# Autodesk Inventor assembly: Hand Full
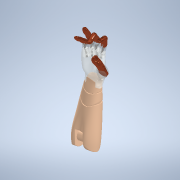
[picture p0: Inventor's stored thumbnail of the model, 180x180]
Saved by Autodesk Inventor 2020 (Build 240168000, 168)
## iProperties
Created: 2019-10
Part Number: Hand Full
Document SubType Name: Assembly
Designer: yello
Author: yello
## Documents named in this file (21)
- D:\1-Cours-2021-22\1STI2D\ETLV\AI\Hand Full.iam
- D:\1-Cours-2021-22\1STI2D\ETLV\AI\Prototype 2 (Realistic Hand)\Palm.ipt
- D:\1-Cours-2021-22\1STI2D\ETLV\AI\Prototype 2 (Realistic Hand)\Wrist Rotation.ipt
- D:\1-Cours-2021-22\1STI2D\ETLV\AI\Prototype 2 (Realistic Hand)\Arm to Wrist Connection.ipt
- D:\1-Cours-2021-22\1STI2D\ETLV\AI\Prototype 2 (Realistic Hand)\Arm.ipt
- D:\1-Cours-2021-22\1STI2D\ETLV\AI\Prototype 2 (Realistic Hand)\Segment Thumb Finger Bottom.ipt
- D:\1-Cours-2021-22\1STI2D\ETLV\AI\Prototype 2 (Realistic Hand)\Segment Thumb Finger Middle.ipt
- D:\1-Cours-2021-22\1STI2D\ETLV\AI\Prototype 2 (Realistic Hand)\Segment Thumb Finger Top.ipt
- D:\1-Cours-2021-22\1STI2D\ETLV\AI\Prototype 2 (Realistic Hand)\Segment Index Finger Middle.ipt
- D:\1-Cours-2021-22\1STI2D\ETLV\AI\Prototype 2 (Realistic Hand)\Segment Index Finger Top.ipt
- D:\1-Cours-2021-22\1STI2D\ETLV\AI\Prototype 2 (Realistic Hand)\Segment Middle Finger Middle.ipt
- D:\1-Cours-2021-22\1STI2D\ETLV\AI\Prototype 2 (Realistic Hand)\Segment Middle Finger Top.ipt
- D:\1-Cours-2021-22\1STI2D\ETLV\AI\Prototype 2 (Realistic Hand)\Segment Ring Finger Middle.ipt
- D:\1-Cours-2021-22\1STI2D\ETLV\AI\Prototype 2 (Realistic Hand)\Segment Ring Finger Top.ipt
- D:\1-Cours-2021-22\1STI2D\ETLV\AI\Prototype 2 (Realistic Hand)\Segment Pinkie Finger Middle.ipt
- D:\1-Cours-2021-22\1STI2D\ETLV\AI\Prototype 2 (Realistic Hand)\Segment Pinkie Finger Top.ipt
- D:\1-Cours-2021-22\1STI2D\ETLV\AI\Prototype 2 (Realistic Hand)\Segment Index Finger Bottom Ball.iam
- D:\1-Cours-2021-22\1STI2D\ETLV\AI\Prototype 2 (Realistic Hand)\Segment Middle Finger Bottom Ball.iam
- D:\1-Cours-2021-22\1STI2D\ETLV\AI\Prototype 2 (Realistic Hand)\Segment Ring Finger Bottom Ball.iam
- D:\1-Cours-2021-22\1STI2D\ETLV\AI\Prototype 2 (Realistic Hand)\Segment Pinkie Finger Bottom Ball.iam
- D:\1-Cours-2021-22\1STI2D\ETLV\AI\Prototype 2 (Realistic Hand)\Bearings.iam
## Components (23 placed, 20 different names)
1. Palm:1 — Rotational:1, Rotational:2, Rotational:17, Rotational:18, Rotational:19, Rotational:20
2. Wrist Rotation:1 — Rotational:1, Mate:1, Mate:2, Mate:4
3. Arm to Wrist Connection:1 — Mate:1, Mate:2, Mate:3
4. Arm:1 — Mate:3, Mate:4
5. Segment Thumb Finger Bottom:1 — Rotational:2, Rotational:3
6. Segment Thumb Finger Middle:1 — Rotational:3, Rotational:4
7. Segment Thumb Finger Top:1 — Rotational:4
8. Segment Index Finger Middle:1 — Rotational:24, Rotational:25, Mate:5, Flush:1
9. Segment Index Finger Top:1 — Rotational:25
10. Segment Middle Finger Middle:1 — Rotational:10, Rotational:23, Mate:6, Flush:2
11. Segment Middle Finger Top:1 — Rotational:10
12. Segment Ring Finger Middle:1 — Rotational:13, Rotational:22, Mate:7, Flush:3
13. Segment Ring Finger Top:1 — Rotational:13
14. Segment Pinkie Finger Middle:1 — Rotational:16, Rotational:21, Mate:8, Flush:4
15. Segment Pinkie Finger Top:1 — Rotational:16
16. Segment Index Finger Bottom Ball:1 [sub-assembly] — Rotational:17, Rotational:24
17. Segment Middle Finger Bottom Ball:1 [sub-assembly] — Rotational:18, Rotational:23
18. Segment Ring Finger Bottom Ball:1 [sub-assembly] — Rotational:19, Rotational:22
19. Segment Pinkie Finger Bottom Ball:1 [sub-assembly] — Rotational:20, Rotational:21
20. Bearings:1 [sub-assembly] — Mate:5, Flush:1
21. Bearings:2 [sub-assembly] — Mate:6, Flush:2
22. Bearings:3 [sub-assembly] — Mate:7, Flush:3
23. Bearings:4 [sub-assembly] — Mate:8, Flush:4
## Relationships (28: RevoluteJoint 16, Mate 8, Flush 4)
- Rotational:1 [RevoluteJoint]: Palm:1 ↔ Wrist Rotation:1
- Mate:1: Wrist Rotation:1 ↔ Arm to Wrist Connection:1
- Mate:2: Wrist Rotation:1 ↔ Arm to Wrist Connection:1
- Mate:3: Arm to Wrist Connection:1 ↔ Arm:1
- Mate:4: Wrist Rotation:1 ↔ Arm:1
- Rotational:2 [RevoluteJoint]: Palm:1 ↔ Segment Thumb Finger Bottom:1
- Rotational:3 [RevoluteJoint]: Segment Thumb Finger Bottom:1 ↔ Segment Thumb Finger Middle:1
- Rotational:4 [RevoluteJoint]: Segment Thumb Finger Middle:1 ↔ Segment Thumb Finger Top:1
- Rotational:10 [RevoluteJoint]: Segment Middle Finger Middle:1 ↔ Segment Middle Finger Top:1
- Rotational:13 [RevoluteJoint]: Segment Ring Finger Middle:1 ↔ Segment Ring Finger Top:1
- Rotational:16 [RevoluteJoint]: Segment Pinkie Finger Middle:1 ↔ Segment Pinkie Finger Top:1
- Rotational:17 [RevoluteJoint]: Palm:1 ↔ Segment Index Finger Bottom Ball:1
- Rotational:18 [RevoluteJoint]: Palm:1 ↔ Segment Middle Finger Bottom Ball:1
- Rotational:19 [RevoluteJoint]: Palm:1 ↔ Segment Ring Finger Bottom Ball:1
- Rotational:20 [RevoluteJoint]: Palm:1 ↔ Segment Pinkie Finger Bottom Ball:1
- Rotational:21 [RevoluteJoint]: Segment Pinkie Finger Middle:1 ↔ Segment Pinkie Finger Bottom Ball:1
- Rotational:22 [RevoluteJoint]: Segment Ring Finger Middle:1 ↔ Segment Ring Finger Bottom Ball:1
- Rotational:23 [RevoluteJoint]: Segment Middle Finger Middle:1 ↔ Segment Middle Finger Bottom Ball:1
- Rotational:24 [RevoluteJoint]: Segment Index Finger Middle:1 ↔ Segment Index Finger Bottom Ball:1
- Rotational:25 [RevoluteJoint]: Segment Index Finger Middle:1 ↔ Segment Index Finger Top:1
- Mate:5: Segment Index Finger Middle:1 ↔ Bearings:1
- Flush:1: Segment Index Finger Middle:1 ↔ Bearings:1
- Mate:6: Segment Middle Finger Middle:1 ↔ Bearings:2
- Flush:2: Segment Middle Finger Middle:1 ↔ Bearings:2
- Mate:7: Segment Ring Finger Middle:1 ↔ Bearings:3
- Flush:3: Segment Ring Finger Middle:1 ↔ Bearings:3
- Mate:8: Segment Pinkie Finger Middle:1 ↔ Bearings:4
- Flush:4: Segment Pinkie Finger Middle:1 ↔ Bearings:4
